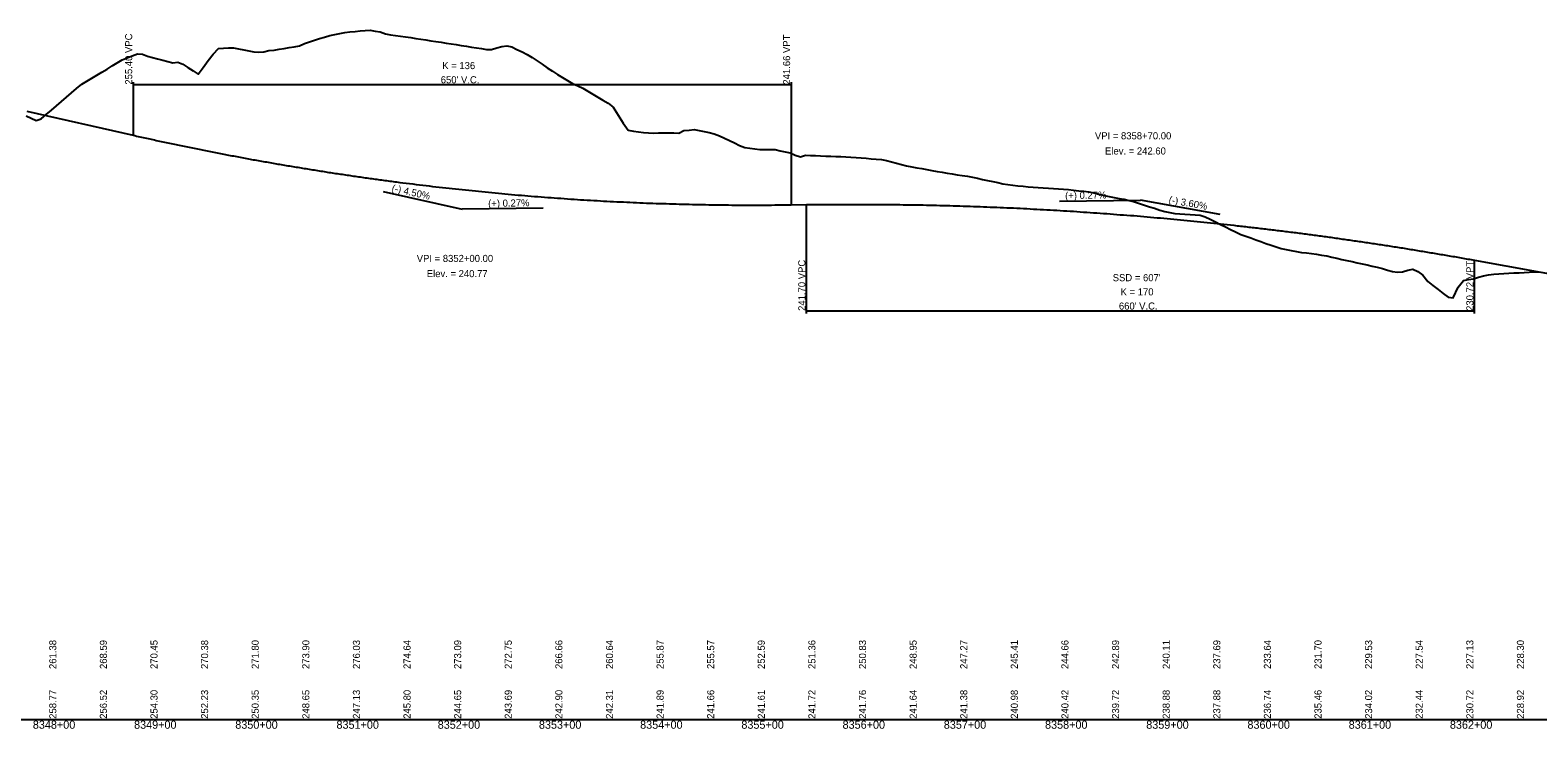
# Model space of a CAD drawing. Extents: x 1876833 to 1953306, y 754739 to 777239.
# Drawn here: x 1879005 to 1880494, y 758480 to 759170 of the extents above; entities that cross this region are included whole.
import ezdxf

# ---------------------------------------------------------------- set-up
doc = ezdxf.new("R2010")
doc.units = 0
for name, color, linetype in [('RD_DDB_GradeTX', 7, 'Continuous'), ('RD_DDB_Profile_EX', 7, 'Continuous'), ('RD_DDB_Profile_Lbl', 7, 'Continuous'), ('RD_DDB_Profile_PR', 7, 'Continuous'), ('RD_DDB_StaTX', 7, 'Continuous'), ('RD_DDB_StripGrade', 7, 'Continuous'), ('RD_DDB_VCLbl', 7, 'Continuous'), ('RD_GPK_Profile_Cell', 7, 'Continuous')]:
    doc.layers.add(name, color=color, linetype=linetype)

msp = doc.modelspace()

# ---------------------------------------------------------------- linework, layer by layer
at = {"layer": 'RD_DDB_GradeTX'}
for p, q in [((1879353.6, 759010.6), (1879431.6, 758993)), ((1880021.6, 759001), (1880101.6, 759002.1)), ((1880180.4, 758988), (1880101.6, 759002.1)), ((1879511.6, 758994.1), (1879431.6, 758993))]:
    msp.add_line(p, q, dxfattribs=at)
at = {"layer": 'RD_DDB_Profile_EX'}
for points in [[(1879200.7, 759152.5), (1879205.7, 759152.6), (1879210.7, 759151.6), (1879215.7, 759150.6), (1879220.7, 759149.6), (1879225.7, 759148.6), (1879230.7, 759148.1), (1879235.7, 759148.4), (1879240.7, 759149.8), (1879245.7, 759150.2), (1879250.7, 759151.1), (1879255.7, 759151.9), (1879260.7, 759152.7), (1879265.7, 759153.5), (1879270.7, 759154.3), (1879275.7, 759156.8), (1879280.7, 759158.4), (1879285.7, 759160), (1879290.7, 759161.5), (1879295.7, 759163.1), (1879300.7, 759164.7), (1879305.7, 759165.7), (1879310.7, 759166.6), (1879315.7, 759167.5), (1879320.7, 759168.1), (1879325.7, 759168.7), (1879330.7, 759169.2), (1879335.7, 759169.7), (1879340.7, 759169.9), (1879345.7, 759169), (1879350.7, 759168.1), (1879355.7, 759166.1), (1879360.7, 759165.4), (1879365.7, 759164.7), (1879370.7, 759163.9), (1879375.7, 759163.2), (1879380.7, 759162.5), (1879385.7, 759161.7), (1879390.7, 759161), (1879395.7, 759160.3), (1879400.7, 759159.5), (1879405.7, 759158.8), (1879410.7, 759158), (1879415.7, 759157.2), (1879420.7, 759156.4), (1879425.7, 759155.6), (1879430.7, 759154.8), (1879435.7, 759154), (1879440.7, 759153.2), (1879445.7, 759152.4), (1879450.7, 759151.7), (1879455.7, 759150.9), (1879460.7, 759150.8), (1879465.7, 759152.3), (1879470.7, 759153.9), (1879475.7, 759154.5), (1879480.7, 759153.4), (1879485.7, 759150.9), (1879490.7, 759148.5), (1879495.7, 759146), (1879500.7, 759143), (1879505.7, 759139.6), (1879510.7, 759136.2), (1879515.7, 759132.8), (1879520.7, 759129.4), (1879525.7, 759126), (1879530.7, 759123), (1879535.7, 759120.1), (1879540.7, 759117.3), (1879545.7, 759114.9), (1879550.7, 759112.5), (1879555.7, 759109.7), (1879560.7, 759106.7), (1879565.7, 759103.8), (1879570.7, 759100.8), (1879575.7, 759097.9), (1879580.7, 759093.8), (1879585.7, 759085.9), (1879590.7, 759078.1), (1879595.7, 759071), (1879600.7, 759070.3), (1879605.7, 759069.6), (1879610.7, 759068.9), (1879615.7, 759068.6), (1879620.7, 759068.3), (1879625.7, 759068.4), (1879630.7, 759068.5), (1879635.7, 759068.5), (1879640.7, 759068.4), (1879645.7, 759068.2), (1879650.7, 759070.7), (1879655.7, 759071.3), (1879660.7, 759071.8), (1879665.7, 759070.7), (1879670.7, 759069.7), (1879675.7, 759068.8), (1879680.7, 759067.4), (1879685.7, 759065.4), (1879690.7, 759063.3), (1879695.7, 759060.9), (1879700.7, 759058.5)], [(1879000.7, 759085.2), (1879005.7, 759082.9), (1879010.7, 759080.7), (1879015.7, 759082.4), (1879020.7, 759086.7), (1879025.7, 759091), (1879030.7, 759095.2), (1879035.7, 759099.5), (1879040.7, 759103.8), (1879045.7, 759108.1), (1879050.7, 759112.4), (1879055.7, 759116.4), (1879060.7, 759119.4), (1879065.7, 759122.4), (1879070.7, 759125.5), (1879075.7, 759128.5), (1879080.7, 759131.5), (1879085.7, 759134.6), (1879090.7, 759137.6), (1879095.7, 759140.5), (1879100.7, 759142.4), (1879105.7, 759144.5), (1879110.7, 759146.5), (1879115.7, 759146.2), (1879120.7, 759144.3), (1879125.7, 759143), (1879130.7, 759141.7), (1879135.7, 759140.2), (1879140.7, 759138.8), (1879145.7, 759137.6), (1879150.7, 759138.2), (1879155.7, 759136.2), (1879160.7, 759132.9), (1879165.7, 759129.6), (1879170.7, 759126.3), (1879175.7, 759133.1), (1879180.7, 759139.9), (1879185.7, 759146.1), (1879190.7, 759151.7), (1879195.7, 759152.2), (1879200.7, 759152.5)], [(1879700.7, 759058.5), (1879705.7, 759056.1), (1879710.7, 759054.1), (1879715.7, 759053.4), (1879720.7, 759052.7), (1879725.7, 759052), (1879730.7, 759052), (1879735.7, 759052.2), (1879740.7, 759052), (1879745.7, 759050.8), (1879750.7, 759049.8), (1879755.7, 759048.6), (1879760.7, 759046.3), (1879765.7, 759044.8), (1879770.7, 759046.6), (1879775.7, 759046.2), (1879780.7, 759046), (1879785.7, 759045.8), (1879790.7, 759045.6), (1879795.7, 759045.4), (1879800.7, 759045.3), (1879805.7, 759045.1), (1879810.7, 759044.9), (1879815.7, 759044.6), (1879820.7, 759044.2), (1879825.7, 759043.8), (1879830.7, 759043.4), (1879835.7, 759043), (1879840.7, 759042.5), (1879845.7, 759042.1), (1879850.7, 759041.3), (1879855.7, 759039.9), (1879860.7, 759038.5), (1879865.7, 759037.2), (1879870.7, 759035.8), (1879875.7, 759034.9), (1879880.7, 759034.1), (1879885.7, 759033.2), (1879890.7, 759032.4), (1879895.7, 759031.3), (1879900.7, 759030.4), (1879905.7, 759029.6), (1879910.7, 759028.8), (1879915.7, 759028), (1879920.7, 759027.1), (1879925.7, 759026.3), (1879930.7, 759025.7), (1879935.7, 759024.6), (1879940.7, 759023.6), (1879945.7, 759022.5), (1879950.7, 759021.4), (1879955.7, 759020.4), (1879960.7, 759019.4), (1879965.7, 759018.3), (1879970.7, 759017.4), (1879975.7, 759016.9), (1879980.7, 759016.3), (1879985.7, 759015.7), (1879990.7, 759015.2), (1879995.7, 759014.7), (1880000.7, 759014.5), (1880005.7, 759014.2), (1880010.7, 759013.9), (1880015.7, 759013.5), (1880020.7, 759013.2), (1880025.7, 759013), (1880030.7, 759012.6), (1880035.7, 759012), (1880040.7, 759011.4), (1880045.7, 759010.9), (1880050.7, 759010.2), (1880055.7, 759009.4), (1880060.7, 759008), (1880065.7, 759006.6), (1880070.7, 759005.5), (1880075.7, 759004.5), (1880080.7, 759003.7), (1880085.7, 759002.9), (1880090.7, 759001.6), (1880095.7, 759000.3), (1880100.7, 758998.8), (1880105.7, 758997.2), (1880110.7, 758995.6), (1880115.7, 758994), (1880120.7, 758992), (1880125.7, 758990.9), (1880130.7, 758989.9), (1880135.7, 758988.9), (1880140.7, 758988.4), (1880145.7, 758988.1), (1880150.7, 758987.9), (1880155.7, 758987.6), (1880160.7, 758987.1), (1880165.7, 758985.6), (1880170.7, 758983.1), (1880175.7, 758980.6), (1880180.7, 758978.1), (1880185.7, 758975.6), (1880190.7, 758973.1), (1880195.7, 758970.6), (1880200.7, 758968.1)], [(1880200.7, 758968.1), (1880205.7, 758966.4), (1880210.7, 758964.8), (1880215.7, 758963), (1880220.7, 758961.2), (1880225.7, 758959.4), (1880230.7, 758957.7), (1880235.7, 758955.9), (1880240.7, 758954.3), (1880245.7, 758953.2), (1880250.7, 758952.2), (1880255.7, 758951.2), (1880260.7, 758950.4), (1880265.7, 758949.9), (1880270.7, 758949.3), (1880275.7, 758948.6), (1880280.7, 758947.8), (1880285.7, 758946.9), (1880290.7, 758945.8), (1880295.7, 758944.6), (1880300.7, 758943.5), (1880305.7, 758942.4), (1880310.7, 758941.4), (1880315.7, 758940), (1880320.7, 758939.1), (1880325.7, 758938.1), (1880330.7, 758937), (1880335.7, 758935.8), (1880340.7, 758934.4), (1880345.7, 758933), (1880350.7, 758931.7), (1880355.7, 758930.9), (1880360.7, 758931.4), (1880365.7, 758932.9), (1880370.7, 758933.8), (1880375.7, 758931.6), (1880380.7, 758928), (1880385.7, 758921.6), (1880390.7, 758917.7), (1880395.7, 758913.8), (1880400.7, 758909.9), (1880405.7, 758906.1), (1880410.7, 758905.6), (1880415.7, 758916), (1880420.7, 758922.7), (1880425.7, 758923.6), (1880430.7, 758924.5), (1880435.7, 758926), (1880440.7, 758927.3), (1880445.7, 758928.4), (1880450.7, 758929), (1880455.7, 758929.3), (1880460.7, 758929.7), (1880465.7, 758930), (1880470.7, 758930.2), (1880475.7, 758930.3), (1880480.7, 758930.6), (1880485.7, 758930.8), (1880490.7, 758931.1), (1880495.7, 758931.3)]]:
    msp.add_lwpolyline(points, dxfattribs=at)
at = {"layer": 'RD_DDB_Profile_PR'}
for p, q in [((1879001.6, 759089.8), (1879106.6, 759066.1)), ((1879756.6, 758997.4), (1879771.6, 758997.6)), ((1880431.6, 758942.7), (1880941.6, 758850.9))]:
    msp.add_line(p, q, dxfattribs=at)
for points in [[(1879106.6, 759066.1), (1879119.6, 759063.2), (1879132.6, 759060.4), (1879145.6, 759057.6), (1879158.6, 759054.9), (1879171.6, 759052.3), (1879184.6, 759049.7), (1879197.6, 759047.2), (1879210.6, 759044.7), (1879223.6, 759042.3), (1879236.6, 759040), (1879249.6, 759037.7), (1879262.6, 759035.5), (1879275.6, 759033.4), (1879288.6, 759031.3), (1879301.6, 759029.2), (1879314.6, 759027.3), (1879327.6, 759025.4), (1879340.6, 759023.5), (1879353.6, 759021.8), (1879366.6, 759020), (1879379.6, 759018.4), (1879392.6, 759016.8), (1879405.6, 759015.3), (1879418.6, 759013.8), (1879431.6, 759012.4), (1879444.6, 759011.1), (1879457.6, 759009.8), (1879470.6, 759008.6), (1879483.6, 759007.4), (1879496.6, 759006.3), (1879509.6, 759005.3), (1879522.6, 759004.3), (1879535.6, 759003.4), (1879548.6, 759002.5), (1879561.6, 759001.8), (1879574.6, 759001), (1879587.6, 759000.4), (1879600.6, 758999.8), (1879613.6, 758999.2), (1879626.6, 758998.8), (1879639.6, 758998.4), (1879652.6, 758998), (1879665.6, 758997.7), (1879678.6, 758997.5), (1879691.6, 758997.3), (1879704.6, 758997.2), (1879717.6, 758997.2), (1879730.6, 758997.2), (1879743.6, 758997.3), (1879756.6, 758997.4)], [(1879771.6, 758997.6), (1879784.8, 758997.8), (1879798, 758997.9), (1879811.2, 758997.9), (1879824.4, 758997.9), (1879837.6, 758997.9), (1879850.8, 758997.8), (1879864, 758997.6), (1879877.2, 758997.4), (1879890.4, 758997.2), (1879903.6, 758996.9), (1879916.8, 758996.5), (1879930, 758996.1), (1879943.2, 758995.7), (1879956.4, 758995.1), (1879969.6, 758994.6), (1879982.8, 758994), (1879996, 758993.3), (1880009.2, 758992.6), (1880022.4, 758991.8), (1880035.6, 758991), (1880048.8, 758990.1), (1880062, 758989.2), (1880075.2, 758988.2), (1880088.4, 758987.2), (1880101.6, 758986.2), (1880114.8, 758985), (1880128, 758983.9), (1880141.2, 758982.6), (1880154.4, 758981.4), (1880167.6, 758980), (1880180.8, 758978.6), (1880194, 758977.2), (1880207.2, 758975.7), (1880220.4, 758974.2), (1880233.6, 758972.6), (1880246.8, 758971), (1880260, 758969.3), (1880273.2, 758967.6), (1880286.4, 758965.8), (1880299.6, 758963.9), (1880312.8, 758962), (1880326, 758960.1), (1880339.2, 758958.1), (1880352.4, 758956.1), (1880365.6, 758954), (1880378.8, 758951.8), (1880392, 758949.6), (1880405.2, 758947.4), (1880418.4, 758945.1), (1880431.6, 758942.7)]]:
    msp.add_spline(points, degree=3, dxfattribs=at)
at = {"layer": 'RD_DDB_VCLbl'}
for p, q in [((1879106.6, 759118.6), (1879106.6, 759066.1)), ((1879106.6, 759116.1), (1879756.6, 759116.1)), ((1879756.6, 759118.6), (1879756.6, 758997.4)), ((1879771.6, 758890.2), (1879771.6, 758997.6)), ((1880431.6, 758890.2), (1880431.6, 758942.7)), ((1879771.6, 758892.7), (1880431.6, 758892.7))]:
    msp.add_line(p, q, dxfattribs=at)
at = {"layer": 'RD_GPK_Profile_Cell'}
msp.add_line((1877681.6, 758489.1), (1884181.6, 758489.1), dxfattribs=at)

# ---------------------------------------------------------------- texts
at = {"layer": 'RD_DDB_GradeTX'}
for s, rotation, p in [('(-) 4.50%', 347.3196, (1879361.5, 759010.8)), ('(+) 0.27%', 0.7787, (1879457.3, 758995.4)), ('(+) 0.27%', 0.7787, (1880027.3, 759003.1)), ('(-) 3.60%', 349.796, (1880129.2, 758999.2))]:
    msp.add_text(s, height=7, rotation=rotation, dxfattribs=at).set_placement(p)
at = {"layer": 'RD_DDB_Profile_Lbl'}
for s, p in [('VPI = 8358+70.00', (1880056.7, 759062.1)), ('Elev. = 242.60', (1880066.7, 759047.1)), ('VPI = 8352+00.00', (1879386.7, 758941)), ('Elev. = 240.77', (1879396.6, 758926))]:
    msp.add_text(s, height=7, dxfattribs=at).set_placement(p)
at = {"layer": 'RD_DDB_StaTX'}
for s, p in [('8348+00', (1879007.4, 758480.1)), ('8349+00', (1879107.4, 758480.1)), ('8350+00', (1879207.4, 758480.1)), ('8351+00', (1879307.4, 758480.1)), ('8352+00', (1879407.4, 758480.1)), ('8353+00', (1879507.4, 758480.1)), ('8354+00', (1879607.4, 758480.1)), ('8355+00', (1879707.4, 758480.1)), ('8356+00', (1879807.4, 758480.1)), ('8357+00', (1879907.4, 758480.1)), ('8358+00', (1880007.4, 758480.1)), ('8359+00', (1880107.4, 758480.1)), ('8360+00', (1880207.4, 758480.1)), ('8361+00', (1880307.4, 758480.1)), ('8362+00', (1880407.4, 758480.1))]:
    msp.add_text(s, height=8, dxfattribs=at).set_placement(p)
at = {"layer": 'RD_DDB_StripGrade'}
for s, p in [('255.40 VPC', (1879105.6, 759116.1)), ('241.66 VPT', (1879755.6, 759116.1)), ('241.70 VPC', (1879770.6, 758892.7)), ('230.72 VPT', (1880430.6, 758892.7)), ('261.38', (1879030.6, 758539.1)), ('268.59', (1879080.6, 758539.1)), ('270.45', (1879130.6, 758539.1)), ('270.38', (1879180.6, 758539.1)), ('271.80', (1879230.6, 758539.1)), ('273.90', (1879280.6, 758539.1)), ('276.03', (1879330.6, 758539.1)), ('274.64', (1879380.6, 758539.1)), ('273.09', (1879430.6, 758539.1)), ('272.75', (1879480.6, 758539.1)), ('266.66', (1879530.6, 758539.1)), ('260.64', (1879580.6, 758539.1)), ('255.87', (1879630.6, 758539.1)), ('255.57', (1879680.6, 758539.1)), ('252.59', (1879730.6, 758539.1)), ('251.36', (1879780.6, 758539.1)), ('250.83', (1879830.6, 758539.1)), ('248.95', (1879880.6, 758539.1)), ('247.27', (1879930.6, 758539.1)), ('245.41', (1879980.6, 758539.1)), ('244.66', (1880030.6, 758539.1)), ('242.89', (1880080.6, 758539.1)), ('240.11', (1880130.6, 758539.1)), ('237.69', (1880180.6, 758539.1)), ('233.64', (1880230.6, 758539.1)), ('231.70', (1880280.6, 758539.1)), ('229.53', (1880330.6, 758539.1)), ('227.54', (1880380.6, 758539.1)), ('227.13', (1880430.6, 758539.1)), ('228.30', (1880480.6, 758539.1)), ('258.77', (1879030.6, 758489.9)), ('256.52', (1879080.6, 758489.9)), ('254.30', (1879130.6, 758489.9)), ('252.23', (1879180.6, 758489.9)), ('250.35', (1879230.6, 758489.9)), ('248.65', (1879280.6, 758489.9)), ('247.13', (1879330.6, 758489.9)), ('245.80', (1879380.6, 758489.9)), ('244.65', (1879430.6, 758489.9)), ('243.69', (1879480.6, 758489.9)), ('242.90', (1879530.6, 758489.9)), ('242.31', (1879580.6, 758489.9)), ('241.89', (1879630.6, 758489.9)), ('241.66', (1879680.6, 758489.9)), ('241.61', (1879730.6, 758489.9)), ('241.72', (1879780.6, 758489.9)), ('241.76', (1879830.6, 758489.9)), ('241.64', (1879880.6, 758489.9)), ('241.38', (1879930.6, 758489.9)), ('240.98', (1879980.6, 758489.9)), ('240.42', (1880030.6, 758489.9)), ('239.72', (1880080.6, 758489.9)), ('238.88', (1880130.6, 758489.9)), ('237.88', (1880180.6, 758489.9)), ('236.74', (1880230.6, 758489.9)), ('235.46', (1880280.6, 758489.9)), ('234.02', (1880330.6, 758489.9)), ('232.44', (1880380.6, 758489.9)), ('230.72', (1880430.6, 758489.9)), ('228.92', (1880480.6, 758489.9))]:
    msp.add_text(s, height=7, rotation=90, dxfattribs=at).set_placement(p)
at = {"layer": 'RD_DDB_VCLbl'}
for s, p in [('K = 136', (1879411.9, 759131.4)), ("650' V.C.", (1879410.4, 759117.4)), ("SSD = 607'", (1880074.3, 758922)), ('K = 170', (1880082.1, 758908)), ("660' V.C.", (1880080.4, 758894))]:
    msp.add_text(s, height=7, dxfattribs=at).set_placement(p)

doc.saveas('drawing.dxf')
